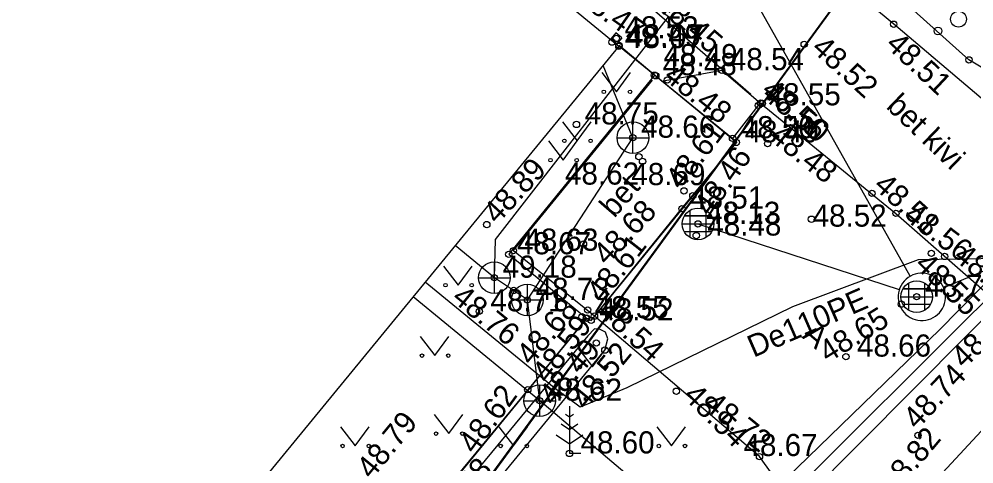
# Model space of a CAD drawing. Extents: x 640876 to 641418, y 6455595 to 6456085.
# Drawn here: x 641190.78 to 641220.97, y 6455879.91 to 6455893.98 of the extents above; entities that cross this region are included whole.
import ezdxf

# ---------------------------------------------------------------- set-up
doc = ezdxf.new("R2010")
doc.units = 0
for name, color, linetype in [('AED', 7, 'Continuous'), ('DKAEV', 7, 'Continuous'), ('DTRASS', 7, 'Continuous'), ('HALJASTUS', 7, 'Continuous'), ('HOONE', 7, 'Continuous'), ('KKAEV', 7, 'Continuous'), ('KORGUS', 7, 'Continuous'), ('KTRASS', 7, 'Continuous'), ('MOOTKORG', 7, 'Continuous'), ('MOOTMPUNKT', 7, 'Continuous'), ('MPKAABEL', 7, 'Continuous'), ('PIIR', 7, 'Continuous'), ('PUU', 7, 'Continuous'), ('SITRASS', 7, 'Continuous'), ('SKKAEV', 7, 'Continuous'), ('TEE', 7, 'Continuous'), ('TTRASS', 7, 'Continuous'), ('VEEKOGU', 7, 'Continuous'), ('VTRASS', 7, 'Continuous')]:
    doc.layers.add(name, color=color, linetype=linetype)

msp = doc.modelspace()

# ---------------------------------------------------------------- linework, layer by layer
at = {"layer": 'AED'}
for p, q in [((641209.645, 6455893.542), (641209.486, 6455893.349)), ((641209.679, 6455893.19), (641209.486, 6455893.349)), ((641209.838, 6455893.383), (641209.645, 6455893.542)), ((641209.838, 6455893.383), (641209.679, 6455893.19))]:
    msp.add_line(p, q, dxfattribs=at)
at = {"layer": 'DKAEV'}
for p, q in [((641211.994, 6455887.068), (641211.994, 6455887.934)), ((641212.494, 6455887.934), (641212.494, 6455887.068)), ((641211.811, 6455887.751), (641212.677, 6455887.751)), ((641212.677, 6455887.251), (641211.811, 6455887.251)), ((641218.907, 6455884.764), (641218.907, 6455885.63)), ((641219.407, 6455885.63), (641219.407, 6455884.764)), ((641218.724, 6455885.447), (641219.59, 6455885.447)), ((641219.59, 6455884.947), (641218.724, 6455884.947))]:
    msp.add_line(p, q, dxfattribs=at)
msp.add_lwpolyline([(641219.28, 6455885.942), (641219.196, 6455885.933), (641219.114, 6455885.914), (641219.035, 6455885.886), (641218.959, 6455885.85), (641218.888, 6455885.805), (641218.822, 6455885.753), (641218.763, 6455885.693), (641218.71, 6455885.628), (641218.665, 6455885.556), (641218.629, 6455885.481), (641218.601, 6455885.401), (641218.582, 6455885.319), (641218.573, 6455885.236), (641218.573, 6455885.152), (641218.582, 6455885.068), (641218.601, 6455884.986), (641218.628, 6455884.907), (641218.665, 6455884.831), (641218.71, 6455884.76), (641218.762, 6455884.694), (641218.821, 6455884.634), (641218.887, 6455884.582), (641218.958, 6455884.537), (641219.034, 6455884.5), (641219.113, 6455884.473), (641219.195, 6455884.454), (641219.279, 6455884.444), (641219.363, 6455884.444), (641219.447, 6455884.454), (641219.529, 6455884.472), (641219.608, 6455884.5), (641219.684, 6455884.537), (641219.755, 6455884.581), (641219.821, 6455884.634), (641219.88, 6455884.693), (641219.933, 6455884.759), (641219.978, 6455884.83), (641220.014, 6455884.906), (641220.042, 6455884.985), (641220.061, 6455885.067), (641220.07, 6455885.151), (641220.07, 6455885.235), (641220.061, 6455885.318), (641220.042, 6455885.4), (641220.015, 6455885.48), (641219.978, 6455885.556), (641219.933, 6455885.627), (641219.881, 6455885.693), (641219.822, 6455885.752), (641219.756, 6455885.805), (641219.685, 6455885.849), (641219.609, 6455885.886), (641219.53, 6455885.914), (641219.448, 6455885.933), (641219.364, 6455885.942)], close=True, dxfattribs=at)
for centre in [(641212.244, 6455887.501), (641219.157, 6455885.197)]:
    msp.add_circle(centre, 0.5, dxfattribs=at)
at = {"layer": 'DTRASS'}
for p, q in [((641218.954, 6455885.847), (641211.718, 6455898.734)), ((641220.013, 6455885.484), (641235.878, 6455892.151)), ((641212.244, 6455887.501), (641218.607, 6455885.426))]:
    msp.add_line(p, q, dxfattribs=at)
at = {"layer": 'HALJASTUS'}
for p, q in [((641209.205, 6455892.285), (641209.668, 6455891.678)), ((641209.668, 6455891.678), (641210.114, 6455892.285)), ((641207.958, 6455890.733), (641208.422, 6455890.127)), ((641208.422, 6455890.127), (641208.867, 6455890.733)), ((641207.518, 6455890.124), (641207.982, 6455889.517)), ((641207.982, 6455889.517), (641208.427, 6455890.124)), ((641204.198, 6455886.168), (641204.662, 6455885.561)), ((641204.662, 6455885.561), (641205.107, 6455886.168)), ((641203.458, 6455883.942), (641203.921, 6455883.335)), ((641203.921, 6455883.335), (641204.367, 6455883.942)), ((641208.445, 6455883.583), (641208.909, 6455882.977)), ((641208.909, 6455882.977), (641209.354, 6455883.583)), ((641203.903, 6455881.476), (641204.366, 6455880.869)), ((641204.366, 6455880.869), (641204.812, 6455881.476)), ((641200.945, 6455881.083), (641201.409, 6455880.477)), ((641201.409, 6455880.477), (641201.854, 6455881.083)), ((641205.945, 6455881.083), (641206.409, 6455880.477)), ((641206.409, 6455880.477), (641206.854, 6455881.083)), ((641210.945, 6455881.083), (641211.409, 6455880.477)), ((641211.409, 6455880.477), (641211.854, 6455881.083))]:
    msp.add_line(p, q, dxfattribs=at)
msp.add_lwpolyline([(641225.967, 6455890.838), (641224.248, 6455890.658), (641220.812, 6455892.688), (641218.042, 6455895.173), (641218.862, 6455895.734), (641223.364, 6455893.565), (641225.967, 6455890.838)], dxfattribs=at)
for centre in [(641209.267, 6455891.678), (641210.096, 6455891.678), (641208.021, 6455890.127), (641208.849, 6455890.127), (641207.581, 6455889.517), (641208.41, 6455889.517), (641204.261, 6455885.561), (641205.09, 6455885.561), (641203.52, 6455883.335), (641204.349, 6455883.335), (641208.508, 6455882.977), (641209.336, 6455882.977), (641203.965, 6455880.869), (641204.794, 6455880.869), (641201.008, 6455880.477), (641201.836, 6455880.477), (641206.008, 6455880.477), (641206.836, 6455880.477), (641211.008, 6455880.477), (641211.836, 6455880.477)]:
    msp.add_circle(centre, 0.055, dxfattribs=at)
at = {"layer": 'HOONE'}
msp.add_lwpolyline([(641149.742, 6455963.717), (641189.36, 6455931.349), (641178.797, 6455918.488), (641209.743, 6455893.117), (641188.509, 6455867.25), (641179.281, 6455874.809), (641167.4, 6455884.521), (641162.961, 6455888.191)], dxfattribs=at)
at = {"layer": 'KKAEV'}
for p, q in [((641210.187, 6455889.727), (641210.187, 6455890.727)), ((641209.687, 6455890.227), (641210.687, 6455890.227)), ((641205.808, 6455885.299), (641205.808, 6455886.299)), ((641205.308, 6455885.799), (641206.308, 6455885.799)), ((641206.851, 6455884.596), (641206.851, 6455885.596)), ((641206.351, 6455885.096), (641207.351, 6455885.096)), ((641207.241, 6455881.408), (641207.241, 6455882.408)), ((641206.741, 6455881.908), (641207.741, 6455881.908))]:
    msp.add_line(p, q, dxfattribs=at)
for centre in [(641210.187, 6455890.227), (641205.808, 6455885.799), (641206.851, 6455885.096), (641207.241, 6455881.908)]:
    msp.add_circle(centre, 0.5, dxfattribs=at)
at = {"layer": 'KORGUS'}
for centre in [(641218.433, 6455893.816), (641209.749, 6455893.15), (641215.603, 6455893.177), (641210.911, 6455892.185), (641211.275, 6455892.05), (641214.224, 6455891.319), (641214.281, 6455891.311), (641214.447, 6455890.041), (641210.375, 6455889.625), (641210.491, 6455889.477), (641211.802, 6455888.545), (641217.745, 6455888.469), (641212.083, 6455888.395), (641211.738, 6455887.984), (641218.504, 6455887.834), (641215.832, 6455887.65), (641205.567, 6455887.479), (641212.19, 6455887.132), (641206.409, 6455886.654), (641208.624, 6455886.867), (641219.625, 6455886.567), (641220.044, 6455886.47), (641206.42, 6455885.396), (641218.674, 6455884.964), (641205.33, 6455884.735), (641208.578, 6455884.563), (641208.726, 6455884.52), (641208.759, 6455884.778), (641208.973, 6455884.583), (641209.03, 6455883.735), (641209.301, 6455883.508), (641216.922, 6455883.304), (641206.865, 6455882.258), (641211.561, 6455882.21), (641219.199, 6455880.813), (641208.181, 6455880.241), (641214.19, 6455880.14)]:
    msp.add_circle(centre, 0.1, dxfattribs=at)
at = {"layer": 'KTRASS'}
for p, q in [((641210.187, 6455890.227), (641209.249, 6455892.515)), ((641206.851, 6455885.096), (641210.187, 6455890.227)), ((641207.241, 6455881.908), (641203.239, 6455885.193)), ((641207.241, 6455881.908), (641206.851, 6455885.096)), ((641216.017, 6455874.483), (641207.241, 6455881.908))]:
    msp.add_line(p, q, dxfattribs=at)
msp.add_lwpolyline([(641206.851, 6455885.096), (641205.808, 6455885.799), (641204.57, 6455886.815)], dxfattribs=at)
at = {"layer": 'MOOTMPUNKT'}
for centre in [(641209.527, 6455893.248), (641209.662, 6455893.366), (641209.743, 6455893.117), (641220.812, 6455892.688), (641212.994, 6455892.362), (641210.869, 6455892.203), (641214.157, 6455891.25), (641208.403, 6455890.646), (641210.187, 6455890.227), (641213.337, 6455890.209), (641213.46, 6455890.077), (641212.244, 6455887.501), (641206.263, 6455886.54), (641205.808, 6455885.799), (641206.851, 6455885.096), (641219.157, 6455885.197), (641208.716, 6455884.516), (641208.866, 6455884.449), (641207.241, 6455881.908)]:
    msp.add_circle(centre, 0.1, dxfattribs=at)
at = {"layer": 'MPKAABEL'}
msp.add_lwpolyline([(641205.808, 6455885.799), (641205.842, 6455887.01), (641211.312, 6455894.052), (641210.501, 6455894.682), (641206.259, 6455898.173), (641205.186, 6455896.853)], dxfattribs=at)
at = {"layer": 'PIIR'}
msp.add_lwpolyline([(641222.58, 6455998.61), (641237.36, 6455995.24), (641235.34, 6455991.29), (641228.11, 6455971.68), (641220.5, 6455953.19), (641213.41, 6455936.25), (641201.58, 6455908.74), (641224.93, 6455905.88), (641191.87, 6455860.58), (641157.02, 6455885.66), (641160.91, 6455891.99), (641102.26, 6455951.82), (641074.95, 6455979.64), (641084.84, 6455991.92)], close=True, dxfattribs=at)
msp.add_lwpolyline([(641315.35, 6455858.84), (641292.55, 6455879.89), (641262.53, 6455885.29), (641239.33, 6455889.47), (641203.18, 6455849.61), (641191.84, 6455860.59), (641224.93, 6455905.88), (641249.88, 6455902.84), (641270.69, 6455899.15), (641280.77, 6455915.37), (641291.33, 6455932.26), (641301.94, 6455948.72)], dxfattribs=at)
at = {"layer": 'PUU'}
for p, q in [((641208.181, 6455881.741), (641208.181, 6455880.241)), ((641208.181, 6455881.391), (641208.056, 6455881.474)), ((641208.305, 6455881.474), (641208.181, 6455881.391)), ((641208.181, 6455880.991), (641207.914, 6455881.169)), ((641208.447, 6455881.169), (641208.181, 6455880.991)), ((641207.756, 6455880.831), (641208.181, 6455880.548)), ((641208.181, 6455880.548), (641208.605, 6455880.831)), ((641208.541, 6455880.241), (641208.181, 6455880.241))]:
    msp.add_line(p, q, dxfattribs=at)
for centre, radius in [((641220.483, 6455893.976), 0.25), ((641219.833, 6455893.601), 0.125)]:
    msp.add_circle(centre, radius, dxfattribs=at)
at = {"layer": 'SITRASS'}
msp.add_lwpolyline([(641160.717, 6455890.02), (641160.061, 6455889.202), (641160.124, 6455887.433), (641162.714, 6455885.215), (641168.31, 6455881.226), (641178.228, 6455873.851), (641188.611, 6455866.439), (641195.817, 6455861.122), (641198.143, 6455862.18), (641205.423, 6455869.555), (641212.959, 6455877.434), (641219.89, 6455884.166), (641222.806, 6455887.129), (641228.363, 6455892.82), (641230.103, 6455894.633)], dxfattribs=at)
at = {"layer": 'SKKAEV'}
for p, q in [((641212.674, 6455887.751), (641211.814, 6455887.751)), ((641211.744, 6455887.501), (641212.744, 6455887.501)), ((641212.674, 6455887.251), (641211.814, 6455887.251)), ((641218.657, 6455885.197), (641219.657, 6455885.197)), ((641219.587, 6455885.447), (641218.727, 6455885.447)), ((641219.587, 6455884.947), (641218.727, 6455884.947))]:
    msp.add_line(p, q, dxfattribs=at)
for centre in [(641212.244, 6455887.501), (641219.157, 6455885.197)]:
    msp.add_circle(centre, 0.5, dxfattribs=at)
at = {"layer": 'TEE'}
for p, q in [((641210.869, 6455892.203), (641206.263, 6455886.54)), ((641214.216, 6455891.325), (641213.322, 6455890.19)), ((641208.716, 6455884.516), (641208.866, 6455884.449))]:
    msp.add_line(p, q, dxfattribs=at)
for points in [[(641227.727, 6455889.418), (641222.234, 6455890.597), (641218.433, 6455893.816), (641212.015, 6455899.131), (641206.417, 6455903.827), (641200.844, 6455908.419), (641200.675, 6455911.228), (641199.697, 6455919.825), (641198.745, 6455928.944), (641198.434, 6455930.44)], [(641210.625, 6455894.463), (641213.912, 6455891.606)], [(641208.866, 6455884.449), (641211.738, 6455887.984), (641213.46, 6455890.077), (641210.869, 6455892.203), (641209.743, 6455893.117)], [(641209.749, 6455893.15), (641210.911, 6455892.185), (641213.47, 6455890.095)], [(641211.095, 6455892.017), (641212.994, 6455892.362), (641214.224, 6455891.319), (641218.504, 6455887.834), (641222.487, 6455884.336)], [(641206.405, 6455886.652), (641210.812, 6455892.047)], [(641213.47, 6455890.095), (641208.973, 6455884.583)], [(641206.263, 6455886.54), (641208.716, 6455884.516), (641206.865, 6455882.258), (641203.523, 6455878.209), (641197.878, 6455871.284), (641193.547, 6455866)], [(641196.58, 6455856.487), (641202.972, 6455864.043), (641209.127, 6455871.296), (641214.674, 6455877.825), (641214.783, 6455878.584), (641214.589, 6455879.582), (641214.19, 6455880.14), (641208.972, 6455884.583), (641206.409, 6455886.654)], [(641208.726, 6455884.52), (641202.594, 6455877.038), (641196.571, 6455869.717), (641193.585, 6455866.047)]]:
    msp.add_lwpolyline(points, dxfattribs=at)
at = {"layer": 'TTRASS'}
for points in [[(641146.983, 6455877.597), (641147.637, 6455878.312), (641148.076, 6455878.791), (641148.587, 6455879.349), (641156.827, 6455888.351), (641157.502, 6455889.088), (641158.299, 6455888.492), (641167.659, 6455881.582), (641177.2, 6455874.303), (641186.795, 6455867.097), (641195.745, 6455860.541), (641196.509, 6455859.853), (641197.119, 6455860.535), (641205.5, 6455869.137), (641213.939, 6455877.707), (641222.42, 6455886.169), (641230.878, 6455894.702), (641235.947, 6455899.687), (641236.146, 6455899.925), (641236.328, 6455899.987), (641239.542, 6455899.756)], [(641240.141, 6455899.285), (641236.489, 6455899.529), (641236.348, 6455899.464), (641230.948, 6455894.114), (641222.434, 6455885.667), (641213.976, 6455877.157), (641205.539, 6455868.624), (641197.23, 6455859.957), (641196.541, 6455859.328), (641186.928, 6455866.582), (641177.306, 6455873.752), (641167.696, 6455880.94), (641158.359, 6455887.923), (641157.562, 6455888.52), (641156.887, 6455887.782), (641148.647, 6455878.781), (641148.136, 6455878.223), (641147.697, 6455877.743), (641147.022, 6455877.006)]]:
    msp.add_lwpolyline(points, dxfattribs=at)
at = {"layer": 'VEEKOGU'}
msp.add_lwpolyline([(641193.238, 6455865.238), (641193.156, 6455864.969), (641193.28, 6455864.775), (641193.473, 6455864.706), (641193.694, 6455864.808), (641197.36, 6455869.076), (641203.419, 6455876.35), (641209.301, 6455883.508), (641209.392, 6455883.865), (641209.323, 6455884.072), (641209.13, 6455884.169), (641208.978, 6455884.183), (641208.764, 6455883.959), (641202.866, 6455876.823), (641196.797, 6455869.475), (641193.238, 6455865.238)], dxfattribs=at)
at = {"layer": 'VTRASS'}
for points in [[(641225.125, 6455884.961), (641224.793, 6455885.293), (641224.379, 6455885.681), (641221.849, 6455886.408), (641219.207, 6455886.366), (641215.232, 6455884.875), (641209.997, 6455882.32), (641208.525, 6455881.71), (641207.703, 6455882.321), (641203.623, 6455885.661)], [(641213.817, 6455872.768), (641215.778, 6455875.106), (641223.644, 6455883.582), (641224.984, 6455884.848)]]:
    msp.add_lwpolyline(points, dxfattribs=at)

# ---------------------------------------------------------------- texts
at = {"layer": 'KORGUS'}
for s, rotation, p in [(' 48.47', 324.8826, (641208.131, 6455894.722)), ('48.45', 319.1619, (641210.87, 6455894.37)), (' 48.51', 316.8043, (641217.954, 6455893.306)), (' 48.52', 317.8991, (641215.603, 6455893.177)), ('48.48', 321.3217, (641211.123, 6455892.092)), (' 48.56', 317.9449, (641214.015, 6455891.828)), ('48.50', 320.6436, (641214.235, 6455891.51)), ('48.61', 52.4992, (641211.713, 6455888.542)), ('48.48', 321.9958, (641214.45, 6455890.184)), ('48.46', 55.0258, (641212.633, 6455887.708)), (' 48.89', 47.069, (641205.719, 6455887.273)), ('48.51', 317.9168, (641217.76, 6455888.659)), (' 48.68', 46.4407, (641209.187, 6455885.968)), (' 48.56', 322.7897, (641218.504, 6455887.834)), ('48.61', 51.973, (641209.214, 6455884.968)), ('48.51', 320.9461, (641220.282, 6455886.398)), ('48.55', 315.836, (641219.06, 6455886.17)), (' 48.76', 320.8406, (641204.22, 6455885.254)), ('48.68', 49.8337, (641206.975, 6455882.989)), ('48.54', 317.7555, (641209.038, 6455884.671)), ('48.68', 44.2315, (641220.662, 6455882.896)), (' 48.65', 31.6793, (641216.126, 6455882.952)), ('48.59', 52.2753, (641207.49, 6455882.418)), ('48.49', 49.5158, (641207.681, 6455881.71)), ('48.52', 50.7504, (641208.706, 6455881.581)), ('48.74', 46.81, (641219.169, 6455880.966)), (' 48.62', 53.8249, (641205.029, 6455879.98)), (' 48.54', 315.1463, (641211.561, 6455882.21)), ('48.72', 321.1679, (641212.38, 6455881.708)), (' 48.79', 50.4906, (641201.76, 6455879.194)), (' 48.82', 49.9795, (641218.293, 6455878.705)), (' 48.68', 46.8287, (641204.002, 6455877.803))]:
    msp.add_text(s, height=0.7, rotation=rotation, dxfattribs=at).set_placement(p)
for s, height, p in [('48.07', 0.75, (641209.93, 6455893.061)), (' 48.49', 0.7, (641210.896, 6455892.488)), ('48.62', 0.7, (641208.04, 6455888.743)), (' 48.69', 0.7, (641209.877, 6455888.726)), (' 48.51', 0.7, (641211.738, 6455887.984)), ('48.52', 0.7, (641215.868, 6455887.414)), ('48.48', 0.7, (641212.54, 6455887.132)), ('48.63', 0.7, (641206.755, 6455886.652)), ('48.71', 0.7, (641205.68, 6455884.735)), ('48.66', 0.7, (641217.272, 6455883.304)), ('48.60', 0.7, (641208.531, 6455880.241))]:
    msp.add_text(s, height=height, dxfattribs=at).set_placement(p)
at = {"layer": 'MOOTKORG'}
for s, p in [(' 48.53', (641209.662, 6455893.366)), (' 48.49', (641209.743, 6455893.117)), (' 48.54', (641212.994, 6455892.362)), (' 48.48', (641210.869, 6455892.203)), (' 48.55', (641214.157, 6455891.25)), (' 48.75', (641208.403, 6455890.646)), (' 48.66', (641210.187, 6455890.227)), (' 48.50', (641213.337, 6455890.209)), (' 48.49', (641213.46, 6455890.077)), (' 48.13', (641212.244, 6455887.501)), (' 48.67', (641206.263, 6455886.54)), (' 49.18', (641205.808, 6455885.799)), (' 48.73', (641206.851, 6455885.096)), (' 48.70', (641219.157, 6455885.197)), (' 48.55', (641208.716, 6455884.516)), (' 48.52', (641208.866, 6455884.449)), (' 48.62', (641207.241, 6455881.908)), (' 48.67', (641213.424, 6455880.159))]:
    msp.add_text(s, height=0.7, dxfattribs=at).set_placement(p)
at = {"layer": 'TEE'}
for s, rotation, p in [('bet kivi', 316.1905, (641218.162, 6455891.182)), ('bet', 48.9231, (641209.599, 6455887.665)), ('A', 319.5881, (641215.506, 6455883.915))]:
    msp.add_text(s, height=0.7, rotation=rotation, dxfattribs=at).set_placement(p)
at = {"layer": 'VTRASS'}
msp.add_text('De110PE', height=0.7, rotation=23.5535, dxfattribs=at).set_placement((641214.003, 6455883.265))

doc.saveas('drawing.dxf')
